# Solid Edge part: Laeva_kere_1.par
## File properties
Author: Olev
Template: Normal.par
Last saved by: haldur
Revision: 72
Application: Solid Edge
Accuracy: 0,990
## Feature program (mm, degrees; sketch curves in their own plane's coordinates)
sketch for "unnamed Protrusion 1" plane through (0, 0, 0) normal (1, 0, 0) x-axis (0, 1, 0)
  line (-292.789, -75.9691) -> (295.211, -75.9691)
  line (295.211, -75.9691) -> (295.211, 0.0309)
  line (295.211, 0.0309) -> (-292.789, 0.0309)
  line (-292.789, 0.0309) -> (-292.789, -75.9691)
extrude "unnamed Protrusion 1" add finite 64 symmetric
replace surface "unnamed ReplaceSurface 1"
replace surface "unnamed ReplaceSurface 2"
fillet "Round_4" radius 0.75  VertexRadius1 = 0.75 mm; VertexRadius2 = 14 mm
sketch for "ExtrudedCutout_6" plane through (0, 6.9681, 0.0309) normal (0, 0, 1) x-axis (1, 0, 0)
  line (0, 0) -> (0, 0)
  line (32, 297.6512) -> (32, -293.2383)
  line (32, -293.2383) -> (69.9153, -293.2383)
  line (69.9153, -293.2383) -> (69.9153, 320.228)
  line (69.9153, 320.228) -> (-79.5587, 320.228)
  line (-79.5587, 320.228) -> (-59.3174, -293.2383)
  line (-59.3174, -293.2383) -> (-32, -293.2383)
  line (-32, -293.2383) -> (-32, 297.6512)
  line (-32, 297.6512) -> (32, 297.6512)
extrude "ExtrudedCutout_6" cut finite 95.5188 along -normal
sketch for "ExtrudedCutout_12" plane through (0, 291.5517, -38.1457) normal (0, 0.995353, 0.096297) x-axis (-1, 0, 0)
  bspline degree 3 poles (0, -35.0746) (-0.7616, -35.0002) (-2.8365, -34.6286) (-2.7972, -29.8346) (-2.984, -26.322) (-4.7766, -18.9941) (-10.7886, -18.4376) (-16.0873, -17.8039) (-21.2755, -17.3918) (-24.6028, -17.0061) knots 0 0.0621 0.2039 0.307 0.3946 0.5706 0.8007 1 multiplicities 4 1 1 1 1 1 1 4
  bspline degree 3 poles (-24.6028, -17.0061) (-25.921, -16.8205) (-27.7223, -16.4983) (-31.9002, -14.1532) (-32.3715, -10.4408) (-32.4454, -7.5981) knots 0 0.2656 0.4327 1 multiplicities 4 1 1 4
  line (-32.4454, -7.5981) -> (-36.1312, -7.5981)
  line (-36.1312, -7.5981) -> (-36.1312, -11.0922)
  line (-36.1312, -11.0922) -> (-36.1312, -44.4182)
  line (-36.1312, -44.4182) -> (0, -44.4182)
  line (36.1312, -44.4182) -> (0, -44.4182)
  line (36.1312, -11.0922) -> (36.1312, -44.4182)
  line (36.1312, -7.5981) -> (36.1312, -11.0922)
  line (32.4454, -7.5981) -> (36.1312, -7.5981)
  bspline degree 3 poles (24.6028, -17.0061) (25.921, -16.8205) (27.7223, -16.4983) (31.9002, -14.1532) (32.3715, -10.4408) (32.4454, -7.5981) knots 0 0.2656 0.4327 1 multiplicities 4 1 1 4
  bspline degree 3 poles (0, -35.0746) (0.7616, -35.0002) (2.8365, -34.6286) (2.7972, -29.8346) (2.984, -26.322) (4.7766, -18.9941) (10.7886, -18.4376) (16.0873, -17.8039) (21.2755, -17.3918) (24.6028, -17.0061) knots 0 0.0621 0.2039 0.307 0.3946 0.5706 0.8007 1 multiplicities 4 1 1 1 1 1 1 4
extrude "ExtrudedCutout_12" cut finite 567.4079 symmetric
sketch used by "unnamed Cutout 1" plane through (0, 0, 0) normal (1, 0, 0) x-axis (0, 1, 0)
extrude "unnamed Cutout 1" cut finite 83.022 symmetric
lofted protrusion "unnamed LoftedProtrusion 1"
fillet "unnamed Round 1"
sketch for "ExtrudedCutout_14" plane through (0, 0, 0) normal (0, -1, 0) x-axis (1, 0, 0)
  line (-40.998, -57.807) -> (-40.998, -82.7833)
  line (-40.998, -82.7833) -> (0, -82.7833)
  line (40.998, -82.7833) -> (0, -82.7833)
  line (40.998, -57.807) -> (40.998, -82.7833)
  line (32, -57.807) -> (40.998, -57.807)
  line (32, -57.807) -> (32, -62.9085)
  arc centre (18.9395, -62.9085) radius 13.0605 from (18.9395, -75.9691) to (32, -62.9085) ccw
  line (18.9395, -75.9691) -> (0, -75.9691)
  line (-18.9395, -75.9691) -> (0, -75.9691)
  arc centre (-18.9395, -62.9085) radius 13.0605 from (-18.9395, -75.9691) to (-32, -62.9085) cw
  line (-32, -57.807) -> (-32, -62.9085)
  line (-32, -57.807) -> (-40.998, -57.807)
extrude "ExtrudedCutout_14" cut finite 497.459 symmetric
fillet "Round_12" radius 7.5
fillet "Round_13" radius 2.5
fillet "Round_14" radius 2
fillet "Round_15" radius 5
sketch for "ExtrudedCutout_15" plane through (0, 0, 0) normal (1, 0, 0) x-axis (0, 1, 0)
  line (0, 0) -> (0, 0)
  line (-240.3196, -78.7634) -> (-240.3196, -84.9579)
  line (-240.3196, -84.9579) -> (-267.5253, -84.9579)
  line (-267.5253, -84.9579) -> (-267.5253, -49.7161)
  line (-267.5253, -49.7161) -> (-246.849, -49.7161)
  line (-246.849, -49.7161) -> (-246.849, -56.1617)
  line (-243.5803, -58.3614) -> (-246.849, -56.1617)
  bspline degree 3 poles (-261.9919, -70.6266) (-262.0878, -62.4727) (-256.4078, -59.1655) (-243.5803, -58.3614) knots 0 1 multiplicities 4 4
  line (-261.9919, -70.6266) -> (-264.1769, -78.7634)
  line (-240.3196, -78.7634) -> (-264.1769, -78.7634)
extrude "ExtrudedCutout_15" cut finite 46.3298 symmetric
fillet "unnamed Round 2"
fillet "Round_17" radius 5
fillet "Round_20" radius 2.5
fillet "Round_21" radius 2
sketch for "ExtrudedCutout_16" plane through (0, 0, 0) normal (1, 0, 0) x-axis (0, 1, 0)
  circle centre (-220.3132, -67.0811) radius 3.8
extrude "ExtrudedCutout_16" cut finite 30.3332 symmetric
fillet "unnamed Round 3"
sketch for "unnamed Cutout 2" plane through (0, 0, 0) normal (1, 0, 0) x-axis (0, 1, 0)
  circle centre (217.8104, -69.3395) radius 3.8
extrude "unnamed Cutout 2" cut to key point symmetric
fillet "Round_23" radius 1
sketch for "ExtrudedCutout_18" plane through (-0.894, 18.9423, -63.3492) normal (0, 0, -1) x-axis (0, 1, 0)
extrude "ExtrudedCutout_18" cut to key point along -normal  Profile_Plane1_Distance = 12.6199 mm
sketch for "ExtrudedCutout_19" plane through (-0.894, 18.9423, -67.3869) normal (0, 0, -1) x-axis (0, 1, 0)
extrude "ExtrudedCutout_19" cut finite 9.7258 along -normal  Profile_Plane1_Distance = 8.5822 mm
chamfer "Chamfer_2" setback 0.05
sketch for "ExtrudedProtrusion_4" plane through (0, 253.0549, -68.0116) normal (0, 1, 0) x-axis (-1, 0, 0)
  circle centre (0, -0.1206) radius 1
extrude "ExtrudedProtrusion_4" add finite 10.9017 along +normal  Profile_Plane1_Distance = 9.1485 mm
sketch for "ExtrudedProtrusion_5" plane through (0, 263.9566, -68.1322) normal (0, 1, 0) x-axis (-1, 0, 0)
  circle centre (0, 0) radius 0.825
extrude "ExtrudedProtrusion_5" add finite 2.8 along +normal
chamfer "Chamfer_3" setback 0.1
fillet "Round_24" radius 0.3
sketch for "ExtrudedCutout_20" plane through (0, 10.8167, 0.0309) normal (0, 0, 1) x-axis (0, 1, 0)
  circle centre (255.5385, 0.894) radius 0.9
extrude "ExtrudedCutout_20" cut finite 1.5 along -normal
sketch for "ExtrudedCutout_21" plane through (0, 10.8167, 0.0309) normal (0, 0, 1) x-axis (0, -1, 0)
extrude "ExtrudedCutout_21" cut finite 4 along -normal
sketch for "ExtrudedProtrusion_6" #1 plane through (0, 295.211, -25.6512) normal (0, 1, 0) x-axis (-1, 0, 0)
extrude "ExtrudedProtrusion_6" add finite 0.3 along +normal
sketch for "ExtrudedProtrusion_7" #1 plane through (0, 295.211, -25.6512) normal (0, 1, 0) x-axis (-1, 0, 0)
extrude "ExtrudedProtrusion_7" add finite 0.3 along +normal
sketch for "ExtrudedCutout_22" plane through (32, 64.3436, -31.4388) normal (1, 0, 0) x-axis (0, 1, 0)
extrude "ExtrudedCutout_22" cut finite 5 along -normal
sketch for "unnamed Cutout 3" plane through (-32, 64.3436, -31.4388) normal (-1, 0, 0) x-axis (0, -1, 0)
  line (-112.1479, 31.4697) -> (-112.1479, 16.2479)
  line (-112.1479, 16.2479) -> (101.7112, 16.2479)
  line (101.7112, 16.2479) -> (101.7112, 31.4697)
  line (101.7112, 31.4697) -> (-112.1479, 31.4697)
extrude "unnamed Cutout 3" cut finite 5 along -normal
sketch for "ExtrudedCutout_26" plane through (27, 69.5619, -7.58) normal (1, 0, 0) x-axis (0, 1, 0)
extrude "ExtrudedCutout_26" cut finite 0.1 along -normal
pattern "unnamed Pattern 1" of "ExtrudedCutout_26"
extrude "unnamed Cutout 4" cut finite 0.1
extrude "unnamed Cutout 5" cut finite 0.1
extrude "unnamed Cutout 6" cut finite 0.1
extrude "unnamed Cutout 7" cut finite 0.1
extrude "unnamed Cutout 8" cut finite 0.1
extrude "unnamed Cutout 9" cut finite 0.1
sketch for "unnamed Cutout 10" plane through (-27, 68.2195, -7.3549) normal (-1, 0, 0) x-axis (0, -1, 0)
extrude "unnamed Cutout 10" cut finite 0.1 along -normal
pattern "unnamed Pattern 2" of "unnamed Cutout 10"
extrude "unnamed Cutout 11" cut finite 0.1
extrude "unnamed Cutout 12" cut finite 0.1
extrude "unnamed Cutout 13" cut finite 0.1
extrude "unnamed Cutout 14" cut finite 0.1
extrude "unnamed Cutout 15" cut finite 0.1
extrude "unnamed Cutout 16" cut finite 0.1
sketch for "unnamed Cutout 17" plane through (32, 64.3436, -31.4388) normal (1, 0, 0) x-axis (0, 1, 0)
  circle centre (-158.3471, 7.0676) radius 2.5
extrude "unnamed Cutout 17" cut finite 0.1 along -normal
extrude "unnamed Cutout 18" cut finite 0.1
extrude "unnamed Cutout 19" cut finite 0.1
extrude "unnamed Cutout 20" cut finite 0.1
extrude "unnamed Cutout 21" cut finite 0.1
extrude "unnamed Cutout 22" cut finite 0.1
extrude "unnamed Cutout 23" cut finite 0.1
extrude "unnamed Cutout 24" cut finite 0.1
extrude "unnamed Cutout 25" cut finite 0.1
extrude "unnamed Cutout 26" cut finite 0.1
extrude "unnamed Cutout 27" cut finite 0.1
extrude "unnamed Cutout 28" cut finite 0.1
extrude "unnamed Cutout 29" cut finite 0.1
extrude "unnamed Cutout 30" cut finite 0.1
extrude "unnamed Cutout 31" cut finite 0.1
extrude "unnamed Cutout 32" cut finite 0.1
extrude "unnamed Cutout 33" cut finite 0.1
extrude "unnamed Cutout 34" cut finite 0.1
extrude "unnamed Cutout 35" cut finite 0.1
extrude "unnamed Cutout 36" cut finite 0.1
extrude "unnamed Cutout 37" cut finite 0.1
extrude "unnamed Cutout 38" cut finite 0.1
extrude "unnamed Cutout 39" cut finite 0.1
extrude "unnamed Cutout 40" cut finite 0.1
extrude "unnamed Cutout 41" cut finite 0.1
extrude "unnamed Cutout 42" cut finite 0.1
extrude "unnamed Cutout 43" cut finite 0.1
extrude "unnamed Cutout 44" cut finite 0.1
extrude "unnamed Cutout 45" cut finite 0.1
extrude "unnamed Cutout 46" cut finite 0.1
extrude "unnamed Cutout 47" cut finite 0.1
extrude "unnamed Cutout 48" cut finite 0.1
extrude "unnamed Cutout 49" cut finite 0.1
extrude "unnamed Cutout 50" cut finite 0.1
extrude "unnamed Cutout 51" cut finite 0.1
extrude "unnamed Cutout 52" cut finite 0.1
extrude "unnamed Cutout 53" cut finite 0.1
extrude "unnamed Cutout 54" cut finite 0.1
extrude "unnamed Cutout 55" cut finite 0.1
extrude "unnamed Cutout 56" cut finite 0.1
extrude "unnamed Cutout 57" cut finite 0.1
extrude "unnamed Cutout 58" cut finite 0.1
extrude "unnamed Cutout 59" cut finite 0.1
extrude "unnamed Cutout 60" cut finite 0.1
extrude "unnamed Cutout 61" cut finite 0.1
extrude "unnamed Cutout 62" cut finite 0.1
extrude "unnamed Cutout 63" cut finite 0.1
extrude "unnamed Cutout 64" cut finite 0.1
extrude "unnamed Cutout 65" cut finite 0.1
extrude "unnamed Cutout 66" cut finite 0.1
extrude "unnamed Cutout 67" cut finite 0.1
extrude "unnamed Cutout 68" cut finite 0.1
extrude "unnamed Cutout 69" cut finite 0.1
extrude "unnamed Cutout 70" cut finite 0.1
extrude "unnamed Cutout 71" cut finite 0.1
extrude "unnamed Cutout 72" cut finite 0.1
extrude "unnamed Cutout 73" cut finite 0.1
extrude "unnamed Cutout 74" cut finite 0.1
extrude "unnamed Cutout 75" cut finite 0.1
extrude "unnamed Cutout 76" cut finite 0.1
extrude "unnamed Cutout 77" cut finite 0.1
extrude "unnamed Cutout 78" cut finite 0.1
extrude "unnamed Cutout 79" cut finite 0.1
extrude "unnamed Cutout 80" cut finite 0.1
extrude "unnamed Cutout 81" cut finite 0.1
sketch for "unnamed Cutout 82" plane through (-32, 116.3495, -31.147) normal (-1, 0, 0) x-axis (0, -1, 0)
  circle centre (-158.3471, 7.0676) radius 2.5
extrude "unnamed Cutout 82" cut finite 0.1 along -normal
extrude "unnamed Cutout 83" cut finite 0.1
extrude "unnamed Cutout 84" cut finite 0.1
extrude "unnamed Cutout 85" cut finite 0.1
extrude "unnamed Cutout 86" cut finite 0.1
extrude "unnamed Cutout 87" cut finite 0.1
extrude "unnamed Cutout 88" cut finite 0.1
extrude "unnamed Cutout 89" cut finite 0.1
extrude "unnamed Cutout 90" cut finite 0.1
extrude "unnamed Cutout 91" cut finite 0.1
extrude "unnamed Cutout 92" cut finite 0.1
extrude "unnamed Cutout 93" cut finite 0.1
extrude "unnamed Cutout 94" cut finite 0.1
extrude "unnamed Cutout 95" cut finite 0.1
extrude "unnamed Cutout 96" cut finite 0.1
extrude "unnamed Cutout 97" cut finite 0.1
extrude "unnamed Cutout 98" cut finite 0.1
extrude "unnamed Cutout 99" cut finite 0.1
extrude "unnamed Cutout 100" cut finite 0.1
extrude "unnamed Cutout 101" cut finite 0.1
extrude "unnamed Cutout 102" cut finite 0.1
extrude "unnamed Cutout 103" cut finite 0.1
extrude "unnamed Cutout 104" cut finite 0.1
extrude "unnamed Cutout 105" cut finite 0.1
extrude "unnamed Cutout 106" cut finite 0.1
extrude "unnamed Cutout 107" cut finite 0.1
extrude "unnamed Cutout 108" cut finite 0.1
extrude "unnamed Cutout 109" cut finite 0.1
extrude "unnamed Cutout 110" cut finite 0.1
extrude "unnamed Cutout 111" cut finite 0.1
extrude "unnamed Cutout 112" cut finite 0.1
extrude "unnamed Cutout 113" cut finite 0.1
extrude "unnamed Cutout 114" cut finite 0.1
extrude "unnamed Cutout 115" cut finite 0.1
extrude "unnamed Cutout 116" cut finite 0.1
extrude "unnamed Cutout 117" cut finite 0.1
extrude "unnamed Cutout 118" cut finite 0.1
extrude "unnamed Cutout 119" cut finite 0.1
extrude "unnamed Cutout 120" cut finite 0.1
extrude "unnamed Cutout 121" cut finite 0.1
extrude "unnamed Cutout 122" cut finite 0.1
extrude "unnamed Cutout 123" cut finite 0.1
extrude "unnamed Cutout 124" cut finite 0.1
extrude "unnamed Cutout 125" cut finite 0.1
extrude "unnamed Cutout 126" cut finite 0.1
extrude "unnamed Cutout 127" cut finite 0.1
extrude "unnamed Cutout 128" cut finite 0.1
extrude "unnamed Cutout 129" cut finite 0.1
extrude "unnamed Cutout 130" cut finite 0.1
extrude "unnamed Cutout 131" cut finite 0.1
extrude "unnamed Cutout 132" cut finite 0.1
extrude "unnamed Cutout 133" cut finite 0.1
extrude "unnamed Cutout 134" cut finite 0.1
extrude "unnamed Cutout 135" cut finite 0.1
extrude "unnamed Cutout 136" cut finite 0.1
extrude "unnamed Cutout 137" cut finite 0.1
extrude "unnamed Cutout 138" cut finite 0.1
extrude "unnamed Cutout 139" cut finite 0.1
extrude "unnamed Cutout 140" cut finite 0.1
extrude "unnamed Cutout 141" cut finite 0.1
extrude "unnamed Cutout 142" cut finite 0.1
extrude "unnamed Cutout 143" cut finite 0.1
extrude "unnamed Cutout 144" cut finite 0.1
extrude "unnamed Cutout 145" cut finite 0.1
extrude "unnamed Cutout 146" cut finite 0.1
sketch for "unnamed Cutout 147" plane through (32, 64.3436, -31.4388) normal (1, 0, 0) x-axis (0, 1, 0)
  circle centre (123.3058, 23.8889) radius 3.5
extrude "unnamed Cutout 147" cut finite 0.1 along -normal
pattern "unnamed Pattern 3" of "unnamed Cutout 147"
extrude "unnamed Cutout 148" cut finite 0.1
extrude "unnamed Cutout 149" cut finite 0.1
extrude "unnamed Cutout 150" cut finite 0.1
extrude "unnamed Cutout 151" cut finite 0.1
extrude "unnamed Cutout 152" cut finite 0.1
extrude "unnamed Cutout 153" cut finite 0.1
sketch for "unnamed Cutout 154" plane through (-32, 397.6446, -31.6091) normal (-1, 0, 0) x-axis (0, -1, 0)
  circle centre (123.3058, 23.8889) radius 3.5
extrude "unnamed Cutout 154" cut finite 0.1 along -normal
pattern "unnamed Pattern 4" of "unnamed Cutout 154"
extrude "unnamed Cutout 155" cut finite 0.1
extrude "unnamed Cutout 156" cut finite 0.1
extrude "unnamed Cutout 157" cut finite 0.1
extrude "unnamed Cutout 158" cut finite 0.1
extrude "unnamed Cutout 159" cut finite 0.1
extrude "unnamed Cutout 160" cut finite 0.1
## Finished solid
Body 1: sheet body, 1 face, 4 edges, 4 vertices.
  Faces by surface: spline 1
  Edges by curve: spline 4
Body 2: sheet body, 1 face, 4 edges, 4 vertices.
  Faces by surface: spline 1
  Edges by curve: spline 4
Body 3: solid body, 675 faces, 1263 edges, 625 vertices.
  Faces by surface: plane 377, cylinder 214, blend 43, swept 31, spline 7, torus 2, cone 1
  Edges by curve: circle 443, line 421, spline 274, intersection 116, curve on surface 9
Bounding box of the edges (mm; curved faces can reach further): 65.415 x 593.834 x 83.990, from (-32.7077, -298.3227, -79.2699) to (32.7077, 295.511, 4.7204).
Cylindrical faces by radius (mm): R0.825 x1, R0.9 x1, R1 x1, R1.15 x1, R1.2844 x56, R2.5 x130, R3.5 x14, R3.5441 x1, R3.8 x2, R4.9584 x1, R5 x4, R13.0605 x2
Conical faces (half-angle, radius in mm at the cone's reference point): 45 deg R0.825 x1
Toroidal faces (ring radius, tube radius in mm): R1.3 r0.3 x2
Planar faces by outward normal: +x 96, +y 46, +z 43, -x 102, -y 17, -z 44, oblique 29
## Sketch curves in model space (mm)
line (-40.998, 0, -57.807) -> (-40.998, 0, -82.7833)
line (-40.998, 0, -82.7833) -> (0, 0, -82.7833)
line (40.998, 0, -82.7833) -> (0, 0, -82.7833)
line (40.998, 0, -57.807) -> (40.998, 0, -82.7833)
line (32, 0, -57.807) -> (40.998, 0, -57.807)
line (32, 0, -57.807) -> (32, 0, -62.9085)
arc centre (18.9395, 0, -62.9085) radius 13.0605 from (18.9395, 0, -75.9691) through (28.4394, 0, -71.8712) to (32, 0, -62.9085)
line (18.9395, 0, -75.9691) -> (0, 0, -75.9691)
line (-18.9395, 0, -75.9691) -> (0, 0, -75.9691)
arc centre (-18.9395, 0, -62.9085) radius 13.0605 from (-18.9395, 0, -75.9691) through (-28.4394, 0, -71.8712) to (-32, 0, -62.9085)
line (-32, 0, -57.807) -> (-32, 0, -62.9085)
line (-32, 0, -57.807) -> (-40.998, 0, -57.807)
ellipse centre (0, -261.1974, -68.0116) radii 7.9575, 6.7153
ellipse centre (0, -169.3337, -63.5982) radii 12.3709, 11.8298
arc centre (0, 267.1618, -63.5982) radius 4.9584 from (0, 262.2034, -63.5982) through (0, 263.5884, -60.1607) to (0, 266.6782, -58.6635)
line (0, 262.2034, -63.5982) -> (0, 262.2034, -72.425)
arc centre (0, 258.6593, -72.425) radius 3.5441 from (0, 262.2034, -72.425) through (0, 261.0914, -75.0029) to (0, 258.6593, -75.9691)
line (0, 258.6593, -75.9691) -> (0, 258.6593, -81.5098)
line (0, 258.6593, -81.5098) -> (0, 301.4567, -81.5098)
line (0, 301.4567, -81.5098) -> (0, 301.4567, -57.1168)
line (0, 300.7249, -55.327) -> (0, 301.4567, -57.1168)
line (0, 300.7249, -55.327) -> (0, 266.6782, -58.6635)
spline (24.6028, 293.1894, -55.0727) -> (30.7115, 292.9329, -52.4216) -> (32.4454, 292.2834, -45.7085)
line (32.4454, 292.2834, -45.7085) -> (36.1312, 292.2834, -45.7085)
line (36.1312, 292.2834, -45.7085) -> (36.1312, 292.6199, -49.1863)
line (36.1312, 292.6199, -49.1863) -> (36.1312, 295.8291, -82.3575)
line (36.1312, 295.8291, -82.3575) -> (0, 295.8291, -82.3575)
line (-36.1312, 295.8291, -82.3575) -> (0, 295.8291, -82.3575)
line (-36.1312, 292.6199, -49.1863) -> (-36.1312, 295.8291, -82.3575)
line (-36.1312, 292.2834, -45.7085) -> (-36.1312, 292.6199, -49.1863)
line (-32.4454, 292.2834, -45.7085) -> (-36.1312, 292.2834, -45.7085)
spline (-24.6028, 293.1894, -55.0727) -> (-30.7115, 292.9329, -52.4216) -> (-32.4454, 292.2834, -45.7085)
spline (0, 294.9293, -73.0573) -> (-7.5505, 293.3699, -56.9394) -> (-24.6028, 293.1894, -55.0727)
spline (0, 294.9293, -73.0573) -> (7.5505, 293.3699, -56.9394) -> (24.6028, 293.1894, -55.0727)
line (0, 295.211, -58.4197) -> (35.9426, 295.211, -58.4197)
line (0, 295.211, -58.4197) -> (-35.6273, 295.211, -58.4197)
line (0, 295.211, -58.4197) -> (0, 295.211, 10.0783)
line (0, 295.211, 10.0783) -> (0, 310.2078, 10.0783)
line (0, 310.2078, 10.0783) -> (0, 310.2078, -67.9591)
line (0, 310.2078, -89.9649) -> (0, 310.2078, -67.9591)
line (0, 248.9984, -89.9649) -> (0, 310.2078, -89.9649)
line (0, 248.9984, -89.9649) -> (0, 248.4946, -75.9691)
line (0, 248.4946, -75.9691) -> (0, 262.8577, -58.4197)
line (0, 262.8577, -58.4197) -> (0, 295.211, -58.4197)
spline (-2.6227, -225.3801, -79.2699) -> (22.7006, -151.7934, -79.2699) -> (32.7077, -76.1707, -79.2699)
spline (-2.6227, -298.3227, 4.7204) -> (23.4894, -232.2237, 4.7204) -> (32.5177, -144.1579, 4.7204)
line (-32, 295.211, 0.0309) -> (32, 295.211, 0.0309)
line (32, 295.211, 0.0309) -> (32, 281.2382, 0.0309)
line (32, 281.2382, 0.0309) -> (-32, 281.0479, 0.0309)
line (-32, 281.0479, 0.0309) -> (-32, 295.211, 0.0309)
line (0, 295.211, -58.4197) -> (0, 295.211, 0.0309)
line (0, 262.8577, -58.4197) -> (0, 295.211, -58.4197)
line (0, 248.4946, -75.9691) -> (0, 262.8577, -58.4197)
line (0, -205.6734, -75.9691) -> (0, -292.789, -75.9691)
line (0, -205.6734, -75.9691) -> (0, 248.4946, -75.9691)
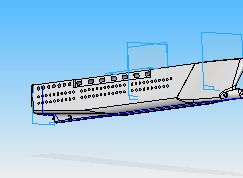
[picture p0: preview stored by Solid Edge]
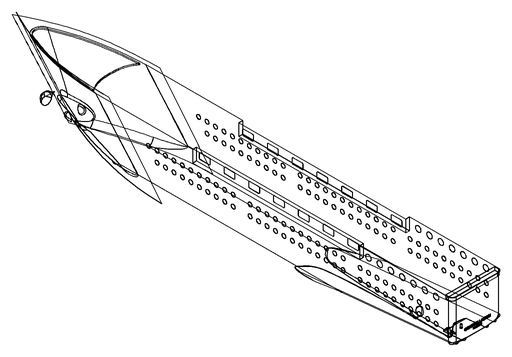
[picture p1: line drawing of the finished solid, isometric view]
